Omron CX-Programmer project NewProject (CX-Programmer 7.20)

# PLC NewPLC1: CJ1M CPU11
I/O table (CPU CJ1M-CPU11): rack 0 slot 0 CJ1W-ETN21(ETN21Mode); rack 0 slot 1 CJ1W-ID211; rack 0 slot 2 CJ1W-OC211; rack 0 slot 3 CJ1W-ID211; rack 0 slot 4 CJ1W-CLK21-V1

## Program NewProgram1 (cyclic task 0)

### Section Section1

### Section END
; rung 0
END(001)

# PLC NewPLC2: CQM1H CPU51

## Program NewProgram1 (no task)

### Section Section1

### Section END
; rung 0
END(01)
